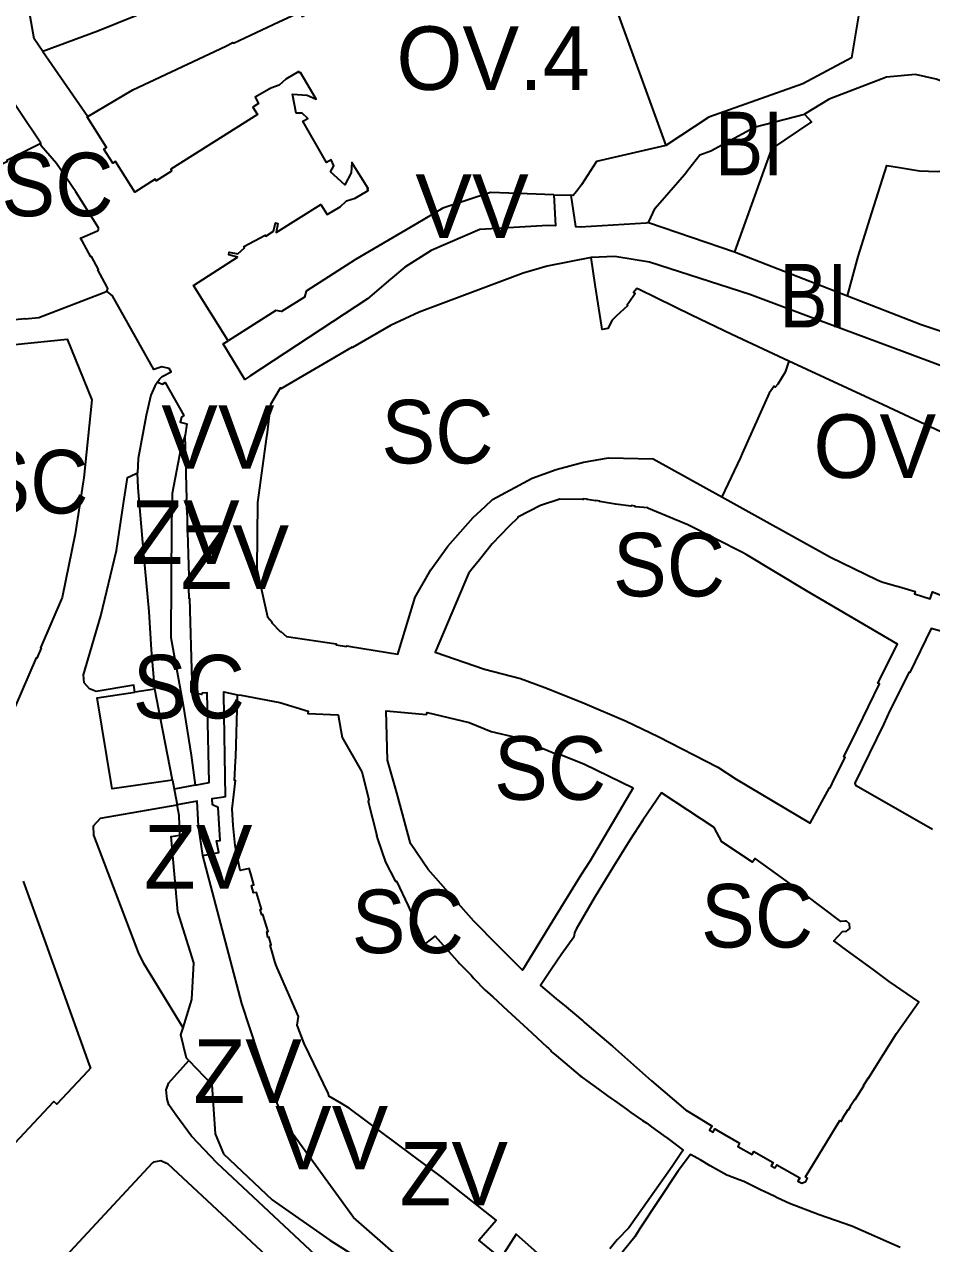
# Model space of a CAD drawing. Extents: x -650451 to -642268, y -1075216 to -1066610.
# Drawn here: x -647351.3 to -647137, y -1070596.5 to -1070308.6 of the extents above; entities that cross this region are included whole.
import ezdxf

# ---------------------------------------------------------------- set-up
doc = ezdxf.new("R2010")
doc.units = 0
doc.header["$LTSCALE"] = 6
doc.layers.add('1', color=7, linetype='Continuous', lineweight=35)
doc.layers.add('2', color=7, linetype='Continuous')

msp = doc.modelspace()

# ---------------------------------------------------------------- linework, layer by layer
at = {"layer": '1'}
for p, q in [((-647219.36, -1070283.36), (-647199.79, -1070337.21)), ((-647346.97, -1070315.05), (-647336.3, -1070330.36)), ((-647347.43, -1070336.69), (-647357.43, -1070321.85)), ((-647226.24, -1070348.88), (-647222.24, -1070348.97)), ((-647203.89, -1070355.43), (-647183.55, -1070362.35)), ((-647183.55, -1070362.35), (-647156.9, -1070372.69)), ((-647320.48, -1070465.55), (-647325.19, -1070466.27)), ((-647316.32, -1070487.1), (-647315.92, -1070489.17)), ((-647310.96, -1070488.27), (-647315.92, -1070489.17))]:
    msp.add_line(p, q, dxfattribs=at)
for points in [[(-647219.36, -1070283.36), (-647197.68, -1070285.3), (-647184.77, -1070288.73), (-647167.15, -1070295.69), (-647154.23, -1070306.63), (-647155.89, -1070316.51), (-647167.43, -1070322.66), (-647189.63, -1070330.53), (-647199.79, -1070337.21)], [(-647346.97, -1070315.05), (-647349, -1070312), (-647350.67, -1070302.55), (-647348.677, -1070297.894), (-647345.27, -1070293.99), (-647343.9, -1070292.96), (-647337.56, -1070288.43), (-647336.22, -1070287.43), (-647334.91, -1070286.51)], [(-647336.3, -1070330.36), (-647325.69, -1070324.05), (-647303.74, -1070313.73), (-647302.03, -1070312.86), (-647301.91, -1070313.05), (-647291.17, -1070307.98), (-647286.23, -1070305.72), (-647285.69, -1070306.76), (-647280.83, -1070303.93), (-647280.52, -1070304.49), (-647274.32, -1070300.9), (-647274.12, -1070301.25), (-647263.72, -1070295.43), (-647259.22, -1070292.91), (-647253.53, -1070290.92), (-647242.698, -1070287.238)], [(-647324.11, -1070306.21), (-647324.94, -1070306.63), (-647333.97, -1070310.22), (-647346.97, -1070315.05)], [(-647303.17, -1070383.32), (-647311.35, -1070370.26), (-647300.94, -1070363.57), (-647303.03, -1070363.02), (-647302.9, -1070362.41), (-647300.86, -1070362.81), (-647299.29, -1070361.36), (-647299.48, -1070361.05), (-647294.43, -1070358.35), (-647294.23, -1070358.66), (-647292.44, -1070357.47), (-647291.96, -1070355.5), (-647291.42, -1070355.65), (-647291.79, -1070357.75), (-647281.3, -1070351.13), (-647279.74, -1070353.48), (-647276.72, -1070351.71), (-647275.2, -1070350.29), (-647273.16, -1070349.63), (-647270.12, -1070347.85), (-647270.32, -1070347.5), (-647270.11, -1070347.38), (-647273.98, -1070341.22), (-647274.09, -1070343.68), (-647275.57, -1070346.5), (-647278.95, -1070343.42), (-647278.24, -1070342.05), (-647278.83, -1070340.56), (-647279.94, -1070341.22), (-647285.5, -1070331.48), (-647284.38, -1070330.84), (-647285.69, -1070329.58), (-647287.06, -1070329.59), (-647288, -1070325.12), (-647284.54, -1070325.36), (-647282.4, -1070326.3), (-647286.1, -1070319.94), (-647286.31, -1070320.06), (-647286.5, -1070319.73), (-647289.53, -1070321.53), (-647291.11, -1070322.98), (-647293.11, -1070323.65), (-647296.79, -1070325.83), (-647296.01, -1070327.28), (-647297.34, -1070328.18), (-647296.22, -1070329.91), (-647316.7, -1070342.8), (-647316.57, -1070343.25), (-647320.18, -1070345.55), (-647320.39, -1070345.17), (-647325.23, -1070348.27), (-647329.81, -1070341.01), (-647330.42, -1070341.42), (-647332.52, -1070338.09), (-647331.89, -1070337.68), (-647336.47, -1070330.46), (-647336.3, -1070330.36)], [(-647113.37, -1070333.96), (-647118.28, -1070328.29), (-647135.94, -1070321.54), (-647140.83, -1070320.47), (-647147.66, -1070321.04), (-647161.17, -1070326.29), (-647167.03, -1070329.81)], [(-647203.89, -1070355.43), (-647202.28, -1070351.98), (-647199.09, -1070348.34), (-647195.37, -1070344.09), (-647194.31, -1070342.72), (-647191.73, -1070339.41), (-647189.18, -1070338.44), (-647179.87, -1070333.43), (-647178.89, -1070332.86), (-647167.03, -1070329.81)], [(-647167.03, -1070329.81), (-647165.36, -1070331.59), (-647174.81, -1070338.01), (-647183.55, -1070362.35)], [(-647384.23, -1070354.52), (-647373.4, -1070349.52), (-647362.04, -1070344.27), (-647359.37, -1070342.96), (-647355.3, -1070340.95), (-647355.42, -1070340.64), (-647347.43, -1070336.69)], [(-647331.81, -1070371.6), (-647331.57, -1070370.99), (-647331.76, -1070370.67), (-647333.93, -1070366.55), (-647333.79, -1070366.47), (-647335.44, -1070363.4), (-647335.58, -1070363.47), (-647337.66, -1070359.76), (-647338.02, -1070359.11), (-647334.05, -1070357.35), (-647333.82, -1070357.02), (-647333.8, -1070356.67), (-647339.15, -1070348.17), (-647343.72, -1070341.43), (-647347.33, -1070337.32), (-647347.43, -1070336.69)], [(-647199.79, -1070337.21), (-647216.16, -1070340.99), (-647219.67, -1070346.48), (-647220.9, -1070348.04), (-647221.64, -1070348.99), (-647222.24, -1070348.97)], [(-647156.9, -1070372.69), (-647154.31, -1070363.46), (-647151.09, -1070353.15), (-647147.6, -1070341.95), (-647144.57, -1070342.42), (-647139.84, -1070343.16), (-647135.62, -1070343.32), (-647132.49, -1070342.91)], [(-647156.9, -1070372.69), (-647139.5, -1070379.46), (-647130.57, -1070382.45), (-647124.22, -1070385.16), (-647119.54, -1070386.4), (-647102.34, -1070391.7), (-647101.63, -1070390.83), (-647099.26, -1070391.68), (-647091.08, -1070375.52), (-647085.09, -1070364.27), (-647096.25, -1070355.36), (-647098.83, -1070353.16), (-647100.99, -1070351.16), (-647106.56, -1070347.82), (-647112.55, -1070345.53), (-647117.31, -1070344.9), (-647126.15, -1070345.04), (-647132, -1070345.56), (-647132.49, -1070342.91)], [(-647226.24, -1070348.88), (-647232.55, -1070348.65), (-647241.16, -1070348.34), (-647252.48, -1070352.03), (-647258.87, -1070355.77), (-647273.05, -1070364.13), (-647284.76, -1070371.59), (-647285.14, -1070372.99), (-647290.59, -1070376.43), (-647291.91, -1070376.15), (-647303.17, -1070383.32)], [(-647226.24, -1070348.88), (-647225.81, -1070356.17), (-647227.66, -1070356.1), (-647243.73, -1070357.08), (-647255.2, -1070362.02), (-647261.44, -1070365.92), (-647264.83, -1070368.81), (-647270.23, -1070373.43), (-647298.06, -1070391.72), (-647299.24, -1070392.5), (-647304.36, -1070384.03), (-647303.17, -1070383.32)], [(-647222.24, -1070348.97), (-647221.1, -1070356.34), (-647220.02, -1070356.38), (-647204.42, -1070355.47), (-647203.89, -1070355.43)], [(-647384.23, -1070354.52), (-647382.24, -1070357.53), (-647382.34, -1070357.65), (-647378.78, -1070361.9), (-647376.13, -1070366.08), (-647370.95, -1070372.26), (-647371.43, -1070372.6), (-647367.08, -1070378.73), (-647365.58, -1070379.37), (-647362.29, -1070379.25), (-647362.28, -1070379.15), (-647351.16, -1070378.04), (-647351.15, -1070378.14), (-647347.85, -1070377.86), (-647332.51, -1070371.94), (-647331.81, -1070371.6)], [(-647217.41, -1070363.66), (-647227.79, -1070365.72), (-647233.5, -1070367.35), (-647258.03, -1070376.56), (-647264.8, -1070379.7), (-647273.83, -1070384.94), (-647273.88, -1070384.86), (-647290.73, -1070394.65), (-647290.88, -1070394.47), (-647291.08, -1070394.88), (-647293.16, -1070398.41), (-647294.03, -1070405.63), (-647294.07, -1070405.89), (-647296.23, -1070421.53), (-647296.37, -1070437.21), (-647293.91, -1070448.53), (-647292.73, -1070449.76), (-647292.84, -1070449.9), (-647290.91, -1070452), (-647290.74, -1070451.97), (-647289.39, -1070453.12), (-647277.65, -1070454.92), (-647277.68, -1070455.11), (-647275.18, -1070455.53), (-647275.15, -1070455.33), (-647274.24, -1070455.48), (-647263.11, -1070457.35), (-647259, -1070443.9), (-647255.31, -1070437.42), (-647251.27, -1070431.86), (-647245.27, -1070425.07), (-647242.43, -1070422.46), (-647240.76, -1070420.84), (-647231.34, -1070415.76), (-647225.69, -1070413.75), (-647219.25, -1070411.99), (-647213.32, -1070410.99), (-647202.8, -1070411.2), (-647186.56, -1070420.18)], [(-647094.97, -1070408.13), (-647096.19, -1070407.37), (-647097.62, -1070406.58), (-647103.89, -1070403.25), (-647111.1, -1070399.66), (-647117.77, -1070396.35), (-647117.34, -1070395.66), (-647125.34, -1070392.73), (-647134.95, -1070389.15), (-647143.43, -1070386), (-647166.72, -1070377.36), (-647179.94, -1070372.43), (-647203.62, -1070364.76), (-647211.86, -1070363.44), (-647217.41, -1070363.66)], [(-647170.69, -1070388.11), (-647184.22, -1070381.82), (-647193.69, -1070377.28), (-647206.08, -1070371.23), (-647206.6, -1070370.98), (-647207.41, -1070371.93), (-647207, -1070372.2), (-647208.54, -1070374.37), (-647208.93, -1070374.84), (-647208.81, -1070375.04), (-647211.45, -1070377.46), (-647212.44, -1070378.48), (-647213.5, -1070380.44), (-647214.78, -1070380.7), (-647214.9, -1070380.14), (-647216.47, -1070370.13), (-647217.41, -1070363.66)], [(-647319.88, -1070393.08), (-647319.38, -1070392.35), (-647318.73, -1070391.73), (-647316.6, -1070390.66), (-647317.08, -1070389.9), (-647318.83, -1070389.47), (-647320.7, -1070390.14), (-647330.5, -1070372.72), (-647331.81, -1070371.6)], [(-647353.52, -1070384.24), (-647341.19, -1070382.93), (-647335.37, -1070397.27), (-647337.25, -1070415.71), (-647337.38, -1070416.66), (-647338.21, -1070421.83), (-647338.29, -1070422.32), (-647339.33, -1070428.94), (-647342.35, -1070443.96), (-647347.46, -1070455.84), (-647347.36, -1070455.88), (-647348.37, -1070458.23), (-647348.48, -1070458.19), (-647353.49, -1070469.66)], [(-647170.69, -1070388.11), (-647171.59, -1070390.7), (-647173.29, -1070393.56), (-647173.93, -1070394.25), (-647174.19, -1070394.05), (-647175.35, -1070395.73), (-647181.72, -1070409.92), (-647182.17, -1070410.91), (-647186.56, -1070420.18)], [(-647101, -1070420.71), (-647104.39, -1070419.17), (-647103.98, -1070418.49), (-647105.38, -1070417.82), (-647105.79, -1070418.65), (-647110.57, -1070416.24), (-647117.43, -1070413.03), (-647131.12, -1070406.58), (-647148.47, -1070398.43), (-647170.69, -1070388.11)], [(-647319.88, -1070393.08), (-647320.52, -1070394.02), (-647321.43, -1070396.13), (-647322.55, -1070400.95), (-647324.46, -1070411.15), (-647324.58, -1070414.52)], [(-647319.88, -1070393.08), (-647318.65, -1070393.57), (-647318.07, -1070393.21), (-647313.6, -1070401), (-647314.22, -1070401.33), (-647314.51, -1070402.54), (-647312.96, -1070402.91), (-647313.34, -1070405.59)], [(-647313.34, -1070405.59), (-647314.33, -1070408.71), (-647316.36, -1070419.37), (-647316.51, -1070426.79), (-647316.72, -1070453.38), (-647313.77, -1070469.37), (-647311.9, -1070481.17), (-647310.96, -1070488.27)], [(-647310.96, -1070488.27), (-647307.63, -1070487.66), (-647308.09, -1070466.49), (-647309.3, -1070466.54), (-647309.36, -1070466.84), (-647311.88, -1070466.27), (-647311.94, -1070463.68), (-647311.64, -1070463.67), (-647312.21, -1070444.18), (-647312.35, -1070444.18), (-647312.44, -1070441.58), (-647312.29, -1070441.58), (-647312.82, -1070423.19), (-647312.94, -1070423.19), (-647313.03, -1070420.74), (-647312.9, -1070420.74), (-647313.34, -1070405.59)], [(-647325.19, -1070466.27), (-647325.46, -1070464.68), (-647334.33, -1070466.16), (-647335.91, -1070465.53), (-647337.17, -1070464.13), (-647337.35, -1070462.19), (-647333.27, -1070448.28), (-647329.55, -1070432.82), (-647327.87, -1070421.72), (-647326.95, -1070415.57), (-647325.04, -1070414.72), (-647324.58, -1070414.52)], [(-647320.48, -1070465.55), (-647321.25, -1070456.27), (-647321.81, -1070447.27), (-647323.12, -1070433.7), (-647324.4, -1070418.06), (-647324.58, -1070414.52)], [(-647186.56, -1070420.18), (-647160.92, -1070434.39), (-647149.82, -1070439.78), (-647148.72, -1070440.26), (-647145.25, -1070441.23), (-647144.79, -1070441.36), (-647140.88, -1070442.51), (-647141.06, -1070443.08), (-647137.31, -1070444.24), (-647136.8, -1070442.59), (-647114.44, -1070451.37), (-647111.71, -1070452.49), (-647108.96, -1070444.81)], [(-647126.52, -1070454.24), (-647137.07, -1070451.29), (-647142.17, -1070461.62), (-647142.33, -1070461.55), (-647146.87, -1070470.66), (-647148.29, -1070473.74), (-647155.17, -1070487.79), (-647155.01, -1070488.27), (-647143.21, -1070494.91), (-647136.79, -1070498.68)], [(-647316.32, -1070487.1), (-647330.57, -1070489.14), (-647330.73, -1070488.15), (-647334.14, -1070467.63), (-647325.19, -1070466.27)], [(-647316.32, -1070487.1), (-647318.59, -1070475.37), (-647320.48, -1070465.55)], [(-647309.17, -1070504.84), (-647305.4, -1070504.14), (-647305.89, -1070501.42), (-647305.05, -1070501.32), (-647305.56, -1070493.53), (-647306.86, -1070492.91), (-647306.91, -1070491.44), (-647304.2, -1070490.98), (-647303.81, -1070490.91), (-647304.21, -1070466.87), (-647304.21, -1070466.72), (-647304.22, -1070466.25), (-647300.93, -1070466.95)], [(-647227.29, -1070601.29), (-647235.16, -1070594.29), (-647238.73, -1070599.96), (-647243.96, -1070595.7), (-647239.85, -1070590.97), (-647249.52, -1070583.31), (-647252.39, -1070581.07), (-647274.56, -1070564.5), (-647276.37, -1070563.43), (-647279.35, -1070561.66), (-647279.47, -1070561.11), (-647285.21, -1070549.25), (-647286.83, -1070544.94), (-647286.58, -1070542.91), (-647291.6, -1070531.38), (-647291.89, -1070530.62), (-647292.15, -1070529.93), (-647292.7, -1070527.94), (-647293.27, -1070526.01), (-647292.98, -1070525.93), (-647293.45, -1070524.32), (-647293.49, -1070524.11), (-647293.77, -1070524.19), (-647293.99, -1070522.89), (-647293.72, -1070522.81), (-647294.95, -1070518.82), (-647295.24, -1070518.9), (-647295.59, -1070517.64), (-647295.31, -1070517.55), (-647296.46, -1070513.62), (-647297.17, -1070513.68), (-647297.67, -1070511.92), (-647297.12, -1070511.78), (-647297.81, -1070509.2), (-647298.17, -1070507.9), (-647300.36, -1070508.44), (-647301.51, -1070502.51), (-647302, -1070497.77), (-647302.2, -1070493.83), (-647301.81, -1070490.57), (-647301.41, -1070487.18), (-647301.67, -1070487.12), (-647301.41, -1070482.56), (-647301.35, -1070481.56), (-647300.95, -1070467.56), (-647300.93, -1070466.95)], [(-647300.93, -1070466.95), (-647300.08, -1070466.97), (-647290.99, -1070468.73), (-647284.28, -1070470.81), (-647284.35, -1070471.36), (-647277.17, -1070471.68), (-647276.55, -1070475.24), (-647276.24, -1070477.03), (-647271.57, -1070485.09), (-647269.97, -1070491.61), (-647270.06, -1070492.08), (-647268.01, -1070500.14), (-647268.09, -1070500.18), (-647267.89, -1070500.96), (-647265.98, -1070506.45), (-647263.68, -1070510.88), (-647263.61, -1070511.02), (-647263.42, -1070510.93), (-647260.68, -1070516.73), (-647256.73, -1070525.84), (-647255.09, -1070524.52), (-647254.3, -1070523.89), (-647251.72, -1070526.77), (-647251.06, -1070527.5), (-647249.15, -1070529.64), (-647248.94, -1070529.88), (-647248.49, -1070530.34), (-647245.8, -1070533.15), (-647245.1, -1070533.87), (-647242.43, -1070536.65), (-647241.93, -1070537.16), (-647240.61, -1070538.24), (-647237.16, -1070541.44), (-647232.47, -1070545.77), (-647231.41, -1070546.76), (-647227.81, -1070550.09), (-647227.49, -1070550.38), (-647227.02, -1070550.82), (-647226.85, -1070551.12), (-647225.68, -1070552.12), (-647224.69, -1070552.95), (-647220, -1070556.92), (-647219.66, -1070557.14), (-647219.36, -1070557.38), (-647218.55, -1070557.96), (-647215.71, -1070560.01), (-647213.52, -1070561.6), (-647212.76, -1070562.15), (-647211.82, -1070562.82), (-647209.09, -1070564.8), (-647208.05, -1070565.55), (-647205.28, -1070567.41), (-647204.26, -1070568.08), (-647203.14, -1070568.92), (-647200.3, -1070571.01), (-647199.34, -1070571.72), (-647195.7, -1070574.42), (-647196.23, -1070575.2), (-647198.31, -1070578.28), (-647208.55, -1070592.81), (-647211.27, -1070595.62), (-647212.98, -1070597.76)], [(-647315.92, -1070489.17), (-647315.84, -1070489.56), (-647315.22, -1070492.88)], [(-647309.17, -1070504.84), (-647310.15, -1070497.9), (-647310.52, -1070492.07), (-647315.22, -1070492.88)], [(-647313.83, -1070545.56), (-647323.06, -1070530.34), (-647324.32, -1070527.73), (-647334.93, -1070500.08), (-647334.94, -1070497.87), (-647333.33, -1070496.01), (-647315.22, -1070492.88)], [(-647313.83, -1070545.56), (-647311.72, -1070538.86), (-647311.26, -1070530.22), (-647315.05, -1070518.13), (-647316.65, -1070500.38), (-647314.61, -1070500.05), (-647314.74, -1070495.42), (-647315.22, -1070492.88)], [(-647213.29, -1070636.7), (-647224.62, -1070631.13), (-647248.47, -1070611.77), (-647257.72, -1070604.16), (-647273.54, -1070590.32), (-647289.23, -1070568.74), (-647294.04, -1070557.72), (-647299.94, -1070539.82), (-647309.17, -1070504.84)], [(-647351.57, -1070510.89), (-647346.61, -1070524.59), (-647336, -1070554.26), (-647335.69, -1070555.11), (-647336.29, -1070555.75), (-647343.66, -1070563.58), (-647344.36, -1070562.93), (-647344.52, -1070563.09), (-647359.36, -1070578.94)], [(-647312.46, -1070553.28), (-647313, -1070552.72), (-647314.36, -1070547.23), (-647313.83, -1070545.56)], [(-647253.3, -1070630.72), (-647257.54, -1070630.35), (-647260.63, -1070628.71), (-647272.84, -1070608.27), (-647305.74, -1070577.49), (-647311.82, -1070571.13), (-647315.54, -1070566.13), (-647317.15, -1070563.76), (-647317.54, -1070562.38), (-647317.82, -1070560.19), (-647317.15, -1070558.53), (-647312.46, -1070553.28)], [(-647312.46, -1070553.28), (-647307.04, -1070558.96), (-647306.21, -1070570.58), (-647304.24, -1070575.28), (-647292.78, -1070586.17), (-647279.11, -1070595.72), (-647264.84, -1070604.72), (-647261.65, -1070606.73), (-647258.83, -1070608.49), (-647253.03, -1070612.42), (-647252.64, -1070612.08), (-647252.04, -1070612.62)], [(-647144.39, -1070597.43), (-647155.82, -1070592.35), (-647163.56, -1070589.75), (-647170.53, -1070587.07), (-647173.48, -1070585.68), (-647174.04, -1070585.41), (-647176.53, -1070584.24), (-647177.26, -1070583.9), (-647177.89, -1070583.58), (-647181.37, -1070581.86), (-647182.42, -1070581.46), (-647185.14, -1070580.45), (-647185.4, -1070580.35), (-647189.29, -1070578.11), (-647191.52, -1070576.82), (-647192.34, -1070576.35), (-647193.96, -1070575.45), (-647196.84, -1070579.31), (-647205.98, -1070593.12), (-647207.14, -1070594.94), (-647210.79, -1070599.46)], [(-647280.26, -1070612.31), (-647317.37, -1070577.72), (-647318.73, -1070577.12), (-647319.1, -1070576.96), (-647320.8, -1070577.25), (-647321.05, -1070577.4), (-647345.68, -1070603.93)]]:
    msp.add_lwpolyline(points, dxfattribs=at)
for points in [[(-647159.9, -1070486.68), (-647157.44, -1070481.69), (-647157.77, -1070481.53), (-647154.52, -1070475.03), (-647149.34, -1070464.34), (-647149.71, -1070464.17), (-647145.08, -1070454.99), (-647161.06, -1070445.63), (-647166.55, -1070442.34), (-647180.82, -1070433.82), (-647181.63, -1070433.31), (-647194.59, -1070426.77), (-647203.89, -1070422.93), (-647204.03, -1070422.88), (-647204.01, -1070422.8), (-647204.94, -1070422.66), (-647204.95, -1070422.73), (-647207.01, -1070422.51), (-647206.99, -1070422.37), (-647207.92, -1070422.24), (-647207.95, -1070422.39), (-647211.66, -1070421.88), (-647215.42, -1070421.3), (-647215.4, -1070421.18), (-647216.32, -1070421.04), (-647216.33, -1070421.11), (-647218.39, -1070420.84), (-647218.38, -1070420.75), (-647219.3, -1070420.62), (-647219.33, -1070420.82), (-647219.45, -1070420.81), (-647224.84, -1070420.76), (-647229.38, -1070422.24), (-647234.76, -1070424.96), (-647234.69, -1070425.02), (-647236.88, -1070427.2), (-647240.8, -1070431.26), (-647243.8, -1070435.02), (-647245.57, -1070437.25), (-647246.38, -1070438.26), (-647254.29, -1070456.83), (-647242.62, -1070460.9), (-647234.1, -1070463.07), (-647228.34, -1070465.19), (-647219.47, -1070468.77), (-647209.17, -1070473.16), (-647201.6, -1070476.78), (-647187.5, -1070483.97), (-647183.17, -1070486.85), (-647165.65, -1070497.22), (-647161.1, -1070488.85), (-647161, -1070488.9)], [(-647207.5, -1070488.86), (-647217.66, -1070506.1), (-647219.86, -1070509.53), (-647226.52, -1070520.38), (-647233.62, -1070531.96), (-647239.46, -1070526.1), (-647245.16, -1070520.39), (-647255.91, -1070508.19), (-647260.08, -1070502.01), (-647263.34, -1070490.07), (-647265.52, -1070482.32), (-647265.82, -1070470.68), (-647256.28, -1070471.58), (-647256.15, -1070471.08), (-647246.26, -1070473.49), (-647241.05, -1070475.59), (-647235, -1070476.99), (-647225.21, -1070481.13), (-647225.06, -1070480.85), (-647219, -1070483.29)], [(-647192.54, -1070566.5), (-647188.82, -1070568.77), (-647189.46, -1070569.75), (-647188.63, -1070570.22), (-647188.2, -1070569.44), (-647187.44, -1070569.87), (-647182.36, -1070572.78), (-647182.78, -1070573.6), (-647179.41, -1070575.5), (-647178.97, -1070574.74), (-647174.43, -1070577.38), (-647174.88, -1070578.16), (-647174.04, -1070578.65), (-647173.58, -1070577.87), (-647168.16, -1070581.01), (-647168.57, -1070581.76), (-647167.69, -1070582.24), (-647166.7, -1070581.81), (-647166.29, -1070581.03), (-647166.76, -1070580.72), (-647158.65, -1070567.47), (-647158.37, -1070567.66), (-647157.89, -1070566.82), (-647157.95, -1070566.77), (-647156.71, -1070564.84), (-647156.64, -1070564.88), (-647156.16, -1070564.14), (-647156.22, -1070564.09), (-647155.13, -1070562.37), (-647155.02, -1070562.45), (-647152.97, -1070559.22), (-647153.08, -1070559.15), (-647151.94, -1070557.38), (-647151.88, -1070557.42), (-647149.74, -1070553.88), (-647145.28, -1070546.93), (-647140.03, -1070539.43), (-647146.99, -1070534.62), (-647150.83, -1070531.79), (-647157.93, -1070526.57), (-647158.66, -1070526.04), (-647160.09, -1070524.98), (-647158.02, -1070522.81), (-647157.07, -1070522.7), (-647156.3, -1070522.08), (-647156.39, -1070520.97), (-647157.11, -1070520.38), (-647157.46, -1070520.39), (-647158.46, -1070520.43), (-647167.1, -1070513.91), (-647178.69, -1070505.54), (-647179.32, -1070506.41), (-647186.56, -1070501.64), (-647188.33, -1070498.23), (-647200.79, -1070490.06), (-647205.2, -1070496.53), (-647208.29, -1070501.21), (-647212.15, -1070507.44), (-647216.72, -1070514.93), (-647220.95, -1070522.23), (-647221.37, -1070523.16), (-647221.54, -1070524.18), (-647224.34, -1070528.07), (-647226.72, -1070531.53), (-647229.41, -1070535.53), (-647226.76, -1070537.76), (-647225.67, -1070538.68), (-647225.27, -1070538.99), (-647223.81, -1070540.24), (-647219.41, -1070543.94), (-647219.08, -1070544.22), (-647217.88, -1070545.23), (-647212.78, -1070549.55), (-647212.36, -1070549.92), (-647203.15, -1070558.09), (-647195.1, -1070564.95)]]:
    msp.add_lwpolyline(points, close=True, dxfattribs=at)

# ---------------------------------------------------------------- texts
at = {"layer": '2'}
for s, p in [('OV.4', (-647263.42, -1070324.09)), ('VV', (-647258.935, -1070359.058)), ('VV', (-647318.965, -1070413.53)), ('OV.4', (-647164.92, -1070415.71)), ('ZV', (-647326.074, -1070436.006)), ('ZV', (-647314.405, -1070441.933)), ('ZV', (-647323.059, -1070512.671)), ('ZV', (-647311.378, -1070563.29)), ('VV', (-647292.101, -1070578.985)), ('ZV', (-647262.678, -1070587.499))]:
    msp.add_text(s, height=15, dxfattribs=at).set_placement(p)
for s, width, p in [('BI', 0.85, (-647188.171, -1070344.245)), ('SC', 0.95, (-647356.728, -1070353.907)), ('BI', 0.85, (-647172.983, -1070380.177)), ('SC', 0.95, (-647266.953, -1070412.279)), ('SC', 0.95, (-647362.639, -1070424.101)), ('SC', 0.95, (-647212.275, -1070443.682)), ('SC', 0.95, (-647325.695, -1070472.498)), ('SC', 0.95, (-647240.353, -1070491.709)), ('SC', 0.95, (-647273.972, -1070527.916)), ('SC', 0.95, (-647191.46, -1070526.59))]:
    msp.add_text(s, height=15, dxfattribs=dict(at, width=width)).set_placement(p)

doc.saveas('drawing.dxf')
